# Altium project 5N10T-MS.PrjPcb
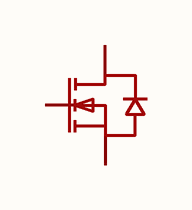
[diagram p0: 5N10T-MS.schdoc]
1 sheet, 1 parts. Net scope: global (net labels, ports and power ports of the same name join across sheets).

## Sheet 5N10T-MS.schdoc
size 127 x 101 mm

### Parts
Q?  5n10t-ms  [SOT-89-3_L4.5-W2.5-P1.50-LS4.1-BR-1]  (value not drawn)

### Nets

Not connected (* = marked no-connect by the designer): Q? 1(G) 2(D) 3(S)

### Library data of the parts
Q? = 5n10t-ms: 数量:1个N沟道;漏源电压(Vdss):100V;连续漏极电流(Id):5A;导通电阻(RDS(on)):140mΩ@10V;耗散功率(Pd):1.2W;阈值电压(Vgs(th)):1.8V;; Manufacturer: MSKSEMI(美森科); AddInBom: yes; ModelId: 08c147d84b0f49b0b2aa8accd0efb262; ModelTransform: 161.417,176.4161,0,0,0,0,-12.953,-0.006,0; Number: 1个N沟道; Drain to Source Voltage: 100V; Current - Continuous Drain(Id): 5A; Pd - Power Dissipation: 1.2W; Gate Threshold Voltage (Vgs(th)): 1.8V; Gate Charge(Qg): 4.3nC@10V; Input Capacitance(Ciss): 206pF; Reverse Transfer Capacitance (Crss@Vds): 1.4pF; Output Capacitance(Coss): 29pF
